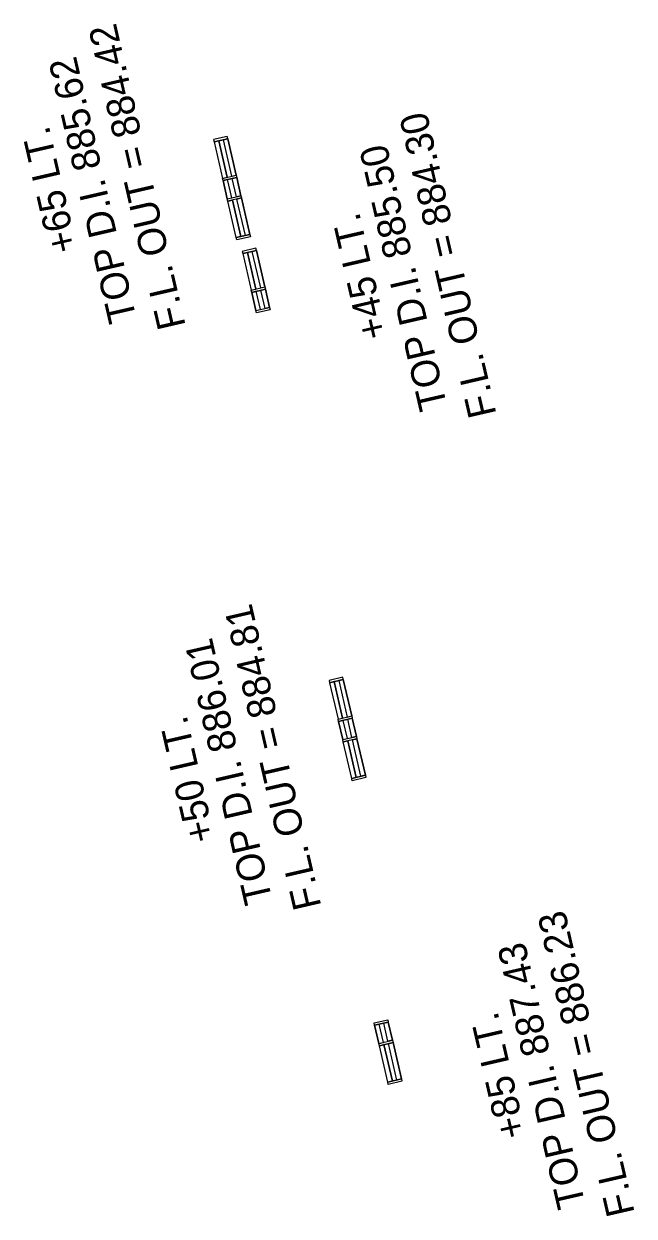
# Model space of a CAD drawing. Extents: x 634644 to 1109508, y 286699 to 700437.
# Drawn here: x 1108975.6 to 1109106, y 699807.9 to 700062.8 of the extents above; entities that cross this region are included whole.
import ezdxf

# ---------------------------------------------------------------- set-up
doc = ezdxf.new("R2010")
doc.units = 0
for name, color, linetype in [('62', 7, 'Continuous'), ('Level 43', 7, 'Continuous'), ('Level 55', 7, 'Continuous'), ('R_Water', 7, 'Continuous')]:
    doc.layers.add(name, color=color, linetype=linetype)

msp = doc.modelspace()

# ---------------------------------------------------------------- linework, layer by layer
at = {"layer": '62'}
for points in [[(1109019.05, 700025.39), (1109018.15, 700029.29)], [(1109025.18, 700001.51), (1109024.28, 700005.4)], [(1109043.74, 699909.78), (1109042.84, 699913.68)], [(1109051.44, 699844.84), (1109050.54, 699848.74)]]:
    msp.add_lwpolyline(points, dxfattribs=at)
at = {"layer": 'Level 43'}
for p, q in [((1109019.05, 700038.73), (1109016.12, 700038.06)), ((1109019.16, 700038.24), (1109016.24, 700037.57)), ((1109016.24, 700037.57), (1109018.04, 700029.77)), ((1109018.04, 700029.77), (1109020.96, 700030.45)), ((1109018.04, 700029.77), (1109020.96, 700030.45)), ((1109018.15, 700029.29), (1109021.07, 700029.96)), ((1109019.05, 700025.39), (1109018.15, 700029.29)), ((1109019.05, 700025.39), (1109021.97, 700026.06)), ((1109020.96, 700017.11), (1109019.16, 700024.9)), ((1109023.88, 700017.78), (1109020.96, 700017.11)), ((1109024, 700017.29), (1109021.07, 700016.62)), ((1109025.18, 700014.85), (1109022.25, 700014.17)), ((1109025.29, 700014.36), (1109022.36, 700013.69)), ((1109022.36, 700013.69), (1109024.16, 700005.89)), ((1109024.16, 700005.89), (1109027.09, 700006.57)), ((1109024.16, 700005.89), (1109027.09, 700006.57)), ((1109024.28, 700005.4), (1109027.2, 700006.08)), ((1109025.18, 700001.51), (1109024.28, 700005.4)), ((1109025.18, 700001.51), (1109028.1, 700002.18)), ((1109043.74, 699923.12), (1109040.81, 699922.44)), ((1109043.85, 699922.63), (1109040.93, 699921.96)), ((1109040.93, 699921.96), (1109042.72, 699914.16)), ((1109042.72, 699914.16), (1109045.65, 699914.84)), ((1109042.72, 699914.16), (1109045.65, 699914.84)), ((1109042.84, 699913.68), (1109045.76, 699914.35)), ((1109043.74, 699909.78), (1109042.84, 699913.68)), ((1109043.74, 699909.78), (1109046.66, 699910.45)), ((1109045.65, 699901.5), (1109043.85, 699909.29)), ((1109048.57, 699902.17), (1109045.65, 699901.5)), ((1109048.68, 699901.68), (1109045.76, 699901.01)), ((1109050.43, 699849.23), (1109053.35, 699849.9)), ((1109050.54, 699848.74), (1109053.46, 699849.42)), ((1109051.44, 699844.84), (1109050.54, 699848.74)), ((1109051.44, 699844.84), (1109054.36, 699845.52)), ((1109051.55, 699844.36), (1109054.48, 699845.03)), ((1109053.35, 699836.56), (1109051.55, 699844.36)), ((1109056.28, 699837.24), (1109053.35, 699836.56)), ((1109056.39, 699836.75), (1109053.47, 699836.07))]:
    msp.add_line(p, q, dxfattribs=at)
at = {"layer": 'R_Water'}
for p, q in [((1109018.18, 700038.02), (1109019.98, 700030.22)), ((1109019.16, 700038.24), (1109020.96, 700030.45)), ((1109017.21, 700037.79), (1109019.01, 700030)), ((1109020.02, 700025.61), (1109019.12, 700029.51)), ((1109021, 700025.84), (1109020.1, 700029.74)), ((1109021.97, 700026.06), (1109021.07, 700029.96)), ((1109022.91, 700017.56), (1109021.11, 700025.35)), ((1109023.88, 700017.78), (1109022.08, 700025.58)), ((1109021.93, 700017.33), (1109020.13, 700025.13)), ((1109023.34, 700013.91), (1109025.14, 700006.12)), ((1109024.31, 700014.14), (1109026.11, 700006.34)), ((1109025.29, 700014.36), (1109027.09, 700006.57)), ((1109026.15, 700001.73), (1109025.25, 700005.63)), ((1109027.13, 700001.96), (1109026.23, 700005.85)), ((1109028.1, 700002.18), (1109027.2, 700006.08)), ((1109041.9, 699922.18), (1109043.7, 699914.39)), ((1109042.87, 699922.41), (1109044.67, 699914.61)), ((1109043.85, 699922.63), (1109045.65, 699914.84)), ((1109044.71, 699910), (1109043.81, 699913.9)), ((1109045.69, 699910.23), (1109044.79, 699914.13)), ((1109046.66, 699910.45), (1109045.76, 699914.35)), ((1109046.62, 699901.72), (1109044.82, 699909.52)), ((1109047.6, 699901.95), (1109045.8, 699909.74)), ((1109048.57, 699902.17), (1109046.77, 699909.97)), ((1109054.36, 699845.52), (1109053.46, 699849.42)), ((1109052.42, 699845.07), (1109051.52, 699848.97)), ((1109053.39, 699845.29), (1109052.49, 699849.19)), ((1109054.33, 699836.79), (1109052.53, 699844.58)), ((1109055.3, 699837.01), (1109053.5, 699844.81)), ((1109056.28, 699837.24), (1109054.48, 699845.03))]:
    msp.add_line(p, q, dxfattribs=at)
for points in [[(1109016.12, 700038.06), (1109016.24, 700037.57), (1109019.16, 700038.24), (1109019.05, 700038.73)], [(1109018.18, 700038.02), (1109019.98, 700030.22), (1109020.96, 700030.45), (1109019.16, 700038.24)], [(1109019.01, 700030), (1109017.21, 700037.79), (1109016.24, 700037.57), (1109018.04, 700029.77)], [(1109020.96, 700030.45), (1109021.07, 700029.96), (1109018.15, 700029.29), (1109018.04, 700029.77)], [(1109018.15, 700029.29), (1109019.05, 700025.39), (1109020.02, 700025.61), (1109019.12, 700029.51)], [(1109021, 700025.84), (1109020.1, 700029.74), (1109021.07, 700029.96), (1109021.97, 700026.06)], [(1109019.16, 700024.9), (1109019.05, 700025.39), (1109021.97, 700026.06), (1109022.08, 700025.58)], [(1109022.91, 700017.56), (1109021.11, 700025.35), (1109022.08, 700025.58), (1109023.88, 700017.78)], [(1109020.13, 700025.13), (1109021.93, 700017.33), (1109020.96, 700017.11), (1109019.16, 700024.9)], [(1109021.07, 700016.62), (1109020.96, 700017.11), (1109023.88, 700017.78), (1109024, 700017.29)], [(1109022.25, 700014.17), (1109022.36, 700013.69), (1109025.29, 700014.36), (1109025.18, 700014.85)], [(1109025.14, 700006.12), (1109023.34, 700013.91), (1109022.36, 700013.69), (1109024.16, 700005.89)], [(1109024.31, 700014.14), (1109026.11, 700006.34), (1109027.09, 700006.57), (1109025.29, 700014.36)], [(1109027.09, 700006.57), (1109027.2, 700006.08), (1109024.28, 700005.4), (1109024.16, 700005.89)], [(1109024.28, 700005.4), (1109025.18, 700001.51), (1109026.15, 700001.73), (1109025.25, 700005.63)], [(1109027.13, 700001.96), (1109026.23, 700005.85), (1109027.2, 700006.08), (1109028.1, 700002.18)], [(1109025.29, 700001.02), (1109025.18, 700001.51), (1109028.1, 700002.18), (1109028.21, 700001.69)], [(1109040.81, 699922.44), (1109040.93, 699921.96), (1109043.85, 699922.63), (1109043.74, 699923.12)], [(1109043.7, 699914.39), (1109041.9, 699922.18), (1109040.93, 699921.96), (1109042.72, 699914.16)], [(1109042.87, 699922.41), (1109044.67, 699914.61), (1109045.65, 699914.84), (1109043.85, 699922.63)], [(1109045.65, 699914.84), (1109045.76, 699914.35), (1109042.84, 699913.68), (1109042.72, 699914.16)], [(1109042.84, 699913.68), (1109043.74, 699909.78), (1109044.71, 699910), (1109043.81, 699913.9)], [(1109045.69, 699910.23), (1109044.79, 699914.13), (1109045.76, 699914.35), (1109046.66, 699910.45)], [(1109043.85, 699909.29), (1109043.74, 699909.78), (1109046.66, 699910.45), (1109046.77, 699909.97)], [(1109044.82, 699909.52), (1109046.62, 699901.72), (1109045.65, 699901.5), (1109043.85, 699909.29)], [(1109047.6, 699901.95), (1109045.8, 699909.74), (1109046.77, 699909.97), (1109048.57, 699902.17)], [(1109045.76, 699901.01), (1109045.65, 699901.5), (1109048.57, 699902.17), (1109048.68, 699901.68)], [(1109053.35, 699849.9), (1109053.46, 699849.42), (1109050.54, 699848.74), (1109050.43, 699849.23)], [(1109053.39, 699845.29), (1109052.49, 699849.19), (1109053.46, 699849.42), (1109054.36, 699845.52)], [(1109050.54, 699848.74), (1109051.44, 699844.84), (1109052.42, 699845.07), (1109051.52, 699848.97)], [(1109051.55, 699844.36), (1109051.44, 699844.84), (1109054.36, 699845.52), (1109054.48, 699845.03)], [(1109052.53, 699844.58), (1109054.33, 699836.79), (1109053.35, 699836.56), (1109051.55, 699844.36)], [(1109055.3, 699837.01), (1109053.5, 699844.81), (1109054.48, 699845.03), (1109056.28, 699837.24)], [(1109053.47, 699836.07), (1109053.35, 699836.56), (1109056.28, 699837.24), (1109056.39, 699836.75)]]:
    msp.add_lwpolyline(points, close=True, dxfattribs=at)

# ---------------------------------------------------------------- texts
at = {"layer": 'Level 55'}
for s, p in [('F.L. OUT = 884.42', (1109010.18, 699998.24)), (' TOP D.I. 885.62', (1109000.2, 699997.48)), ('F.L. OUT = 884.30', (1109076.61, 699979.36)), ('+65 LT.', (1108987.03, 700014.54)), (' TOP D.I. 885.50', (1109066.6, 699978.75)), ('+45 LT.', (1109053.36, 699996.06)), ('F.L. OUT = 884.81', (1109039.18, 699874.17)), (' TOP D.I. 886.01', (1109029.24, 699873.18)), ('+50 LT.', (1109016.47, 699888.49)), ('F.L. OUT = 886.23', (1109106.17, 699808.62)), (' TOP D.I. 887.43', (1109096.13, 699808.15)), ('+85 LT.', (1109082.95, 699825.2))]:
    msp.add_text(s, height=6, rotation=103, dxfattribs=at).set_placement(p)

doc.saveas('drawing.dxf')
